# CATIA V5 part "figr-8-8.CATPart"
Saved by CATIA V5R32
Part number: Part1
Bounding box of the stored display mesh (mm): x 4.549 to 89.781, y -52.238 to 26.36, z 54 to 147.773
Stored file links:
  D:\PROJECTS\Project 2022\CATIA V5 6R 2022\Resources\Part Files\c08_catia_v5_6r2022_prt\figr-8-8.CATPart
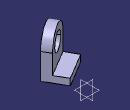
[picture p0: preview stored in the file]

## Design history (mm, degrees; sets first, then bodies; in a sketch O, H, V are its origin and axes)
Body1 (main body)
  Sketch1 on yz-plane, origin (0, 0, 0), H (0, 1, 0), V (0, 0, 1)
    point P1 (-104.4861, 0)
    line L1 (-104.4861, 0) -> (-104.4861, 44.267)
    arc A1 centre (-69.7903, 44.267) radius 34.6958 from (-104.4861, 44.267) to (-35.0946, 44.267) cw
    line L2 (-35.0946, 44.267) -> (-35.0946, 0)
    point P5 (-35.0946, 0)
    line L3 (-35.0946, 0) -> (-104.4861, 0)
    circle A2 centre (-69.7903, 44.267) radius 19.5413
    coincidence: P1 H, P5 H
    vertical: L1 V
    tangency: A1 L1, L2 A1
    horizontal: L3 H
  Pad1: profile Sketch1, direction (1, 0, 0), length 20
  Sketch2 on face of Pad1, origin (0, 0, 0), H (0, -1, 0), V (0, 0, 1)
    point P1 (35.0946, 0)
    line L1 (35.0946, 0) -> (104.4861, 0)
    line L2 (104.4861, 0) -> (104.4861, -15)
    line L3 (104.4861, -15) -> (35.0946, -15)
    line L4 (35.0946, -15) -> (35.0946, 0)
    reference projected line E1 (35.0946, 0) -> (35.0946, 44.267) from edge [face of Pad1 | face of Pad1]
    reference projected line E2 (104.4861, 44.267) -> (104.4861, 0) from edge [face of Pad1 | face of Pad1]
    distance L3 L1 = 15
    coincidence: P1 H, L4 E1, L2 E2
    horizontal: L1 H, L3 H
    vertical: L2 V, L4 V
  Pad2: profile Sketch2, direction (1, 0, 0), length 50
  Translate1: Direction xy-plane, ToTransfor Pad2, Length 69
  Rotate1: Axis edge, ToTransfor Translate1, Angle 121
